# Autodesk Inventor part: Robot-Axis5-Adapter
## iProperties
Shininess: 21.0
Length Units: 11269
Angle Units: 11279
Time Units: 11290
Mass Units: 11283
Length Display Precision: 3
Angle Display Precision: 2
Created: 2001-08
Part Number: Robot-Axis5-Adapter
Document SubType Name: ﾓﾃﾞﾘﾝｸﾞ
Designer: Administrator
Density: 1 g/cm^3
Density: 0.0
Volumn: 0.0
Area: 0.0
PropertySet Name: Model Information
Control State: 0
Master: False
Checked Out: False
Author: Administrator
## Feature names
1. Extrusion1
2. Extrusion2
3. Extrusion3
